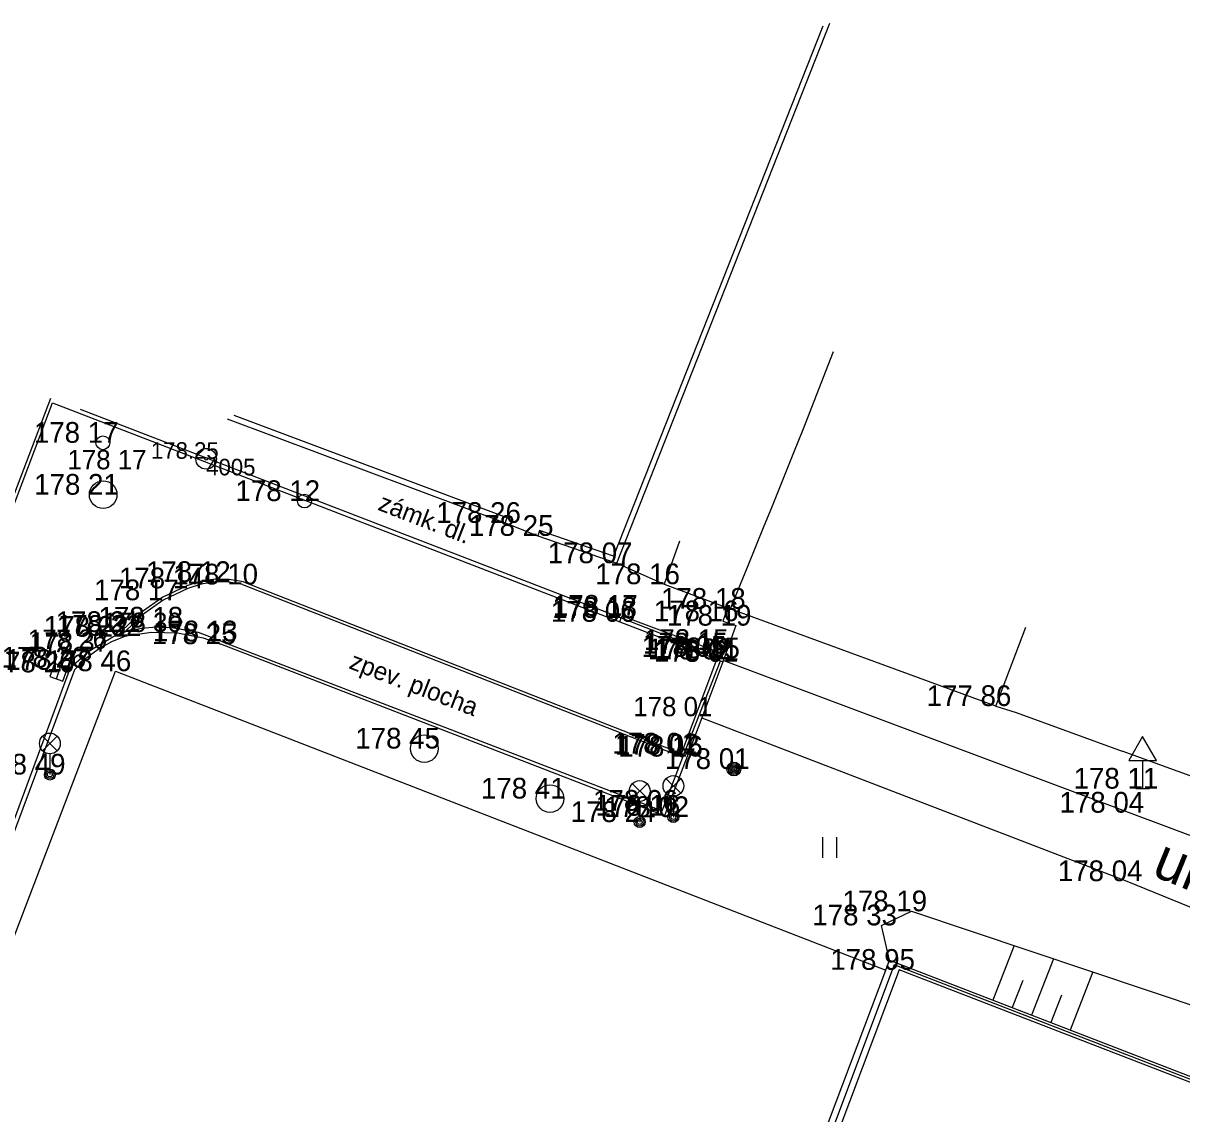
# Model space of a CAD drawing. Extents: x -537755 to -537431, y -1180722 to -1180510.
# Drawn here: x -537546.93 to -537504.97, y -1180552.16 to -1180512.68 of the extents above; entities that cross this region are included whole.
import ezdxf

# ---------------------------------------------------------------- set-up
doc = ezdxf.new("R2010")
doc.units = 0
for name, color, linetype in [('Vrstva 1', 7, 'Continuous'), ('Vrstva 10', 7, 'Continuous'), ('Vrstva 11', 7, 'Continuous'), ('Vrstva 14', 7, 'Continuous'), ('Vrstva 15', 7, 'Continuous'), ('Vrstva 21', 7, 'Continuous'), ('Vrstva 22', 7, 'Continuous'), ('Vrstva 23', 7, 'Continuous'), ('Vrstva 25', 7, 'Continuous'), ('Vrstva 27', 7, 'Continuous'), ('Vrstva 28', 7, 'Continuous'), ('Vrstva 3', 7, 'Continuous'), ('Vrstva 33', 7, 'Continuous'), ('Vrstva 34', 7, 'Continuous'), ('Vrstva 36', 7, 'Continuous'), ('Vrstva 40', 7, 'Continuous'), ('Vrstva 49', 7, 'Continuous'), ('Vrstva 7', 7, 'Continuous'), ('Vrstva 8', 7, 'Continuous')]:
    doc.layers.add(name, color=color, linetype=linetype)

msp = doc.modelspace()

# ---------------------------------------------------------------- linework, layer by layer
at = {"layer": 'Vrstva 1'}
for p, q in [((-537544.04, -1180527.87), (-537544.04, -1180527.87)), ((-537542.99, -1180528.83), (-537542.99, -1180528.83)), ((-537544.03, -1180529.75), (-537544.03, -1180529.75)), ((-537536.74, -1180529.98), (-537536.74, -1180529.98)), ((-537529.47, -1180530.77), (-537529.47, -1180530.77)), ((-537528.29, -1180531.24), (-537528.29, -1180531.24)), ((-537525.43, -1180532.23), (-537525.43, -1180532.23)), ((-537540.96, -1180533.14), (-537540.96, -1180533.14)), ((-537539.98, -1180532.91), (-537539.98, -1180532.91)), ((-537538.99, -1180533), (-537538.99, -1180533)), ((-537523.71, -1180532.99), (-537523.71, -1180532.99)), ((-537541.86, -1180533.57), (-537541.86, -1180533.57)), ((-537521.33, -1180533.88), (-537521.33, -1180533.88)), ((-537525.32, -1180534.35), (-537525.32, -1180534.35)), ((-537525.27, -1180534.21), (-537525.27, -1180534.21)), ((-537525.24, -1180534.13), (-537525.24, -1180534.13)), ((-537521.59, -1180534.33), (-537521.59, -1180534.33)), ((-537543.25, -1180534.72), (-537543.25, -1180534.72)), ((-537541.71, -1180534.72), (-537541.71, -1180534.72)), ((-537541.7, -1180534.56), (-537541.7, -1180534.56)), ((-537521.12, -1180534.49), (-537521.12, -1180534.49)), ((-537543.68, -1180534.89), (-537543.68, -1180534.89)), ((-537543.21, -1180534.86), (-537543.21, -1180534.86)), ((-537539.77, -1180535.16), (-537539.77, -1180535.16)), ((-537539.73, -1180535.06), (-537539.73, -1180535.06)), ((-537544.42, -1180535.33), (-537544.42, -1180535.33)), ((-537544.35, -1180535.43), (-537544.35, -1180535.43)), ((-537522.03, -1180535.62), (-537522.03, -1180535.62)), ((-537521.98, -1180535.5), (-537521.98, -1180535.5)), ((-537521.95, -1180535.37), (-537521.95, -1180535.37)), ((-537545.21, -1180536.01), (-537545.21, -1180536.01)), ((-537521.81, -1180535.71), (-537521.81, -1180535.71)), ((-537521.59, -1180535.8), (-537521.59, -1180535.8)), ((-537521.58, -1180535.75), (-537521.58, -1180535.75)), ((-537521.54, -1180535.67), (-537521.54, -1180535.67)), ((-537545.64, -1180536.18), (-537545.64, -1180536.18)), ((-537545.07, -1180536.09), (-537545.07, -1180536.09)), ((-537543.58, -1180536.14), (-537543.58, -1180536.14)), ((-537511.71, -1180537.4), (-537511.71, -1180537.4)), ((-537522.5, -1180537.77), (-537522.5, -1180537.77)), ((-537532.4, -1180538.94), (-537532.4, -1180538.94)), ((-537523.09, -1180539.12), (-537523.09, -1180539.12)), ((-537523, -1180539.16), (-537523, -1180539.16)), ((-537522.88, -1180539.23), (-537522.88, -1180539.23)), ((-537521.19, -1180539.68), (-537521.19, -1180539.68)), ((-537545.96, -1180539.88), (-537545.96, -1180539.88)), ((-537506.39, -1180540.39), (-537506.39, -1180540.39)), ((-537527.85, -1180540.75), (-537527.85, -1180540.75)), ((-537523.79, -1180541.19), (-537523.79, -1180541.19)), ((-537523.7, -1180541.37), (-537523.7, -1180541.37)), ((-537523.38, -1180541.42), (-537523.38, -1180541.42)), ((-537506.9, -1180541.26), (-537506.9, -1180541.26)), ((-537524.61, -1180541.6), (-537524.61, -1180541.6)), ((-537524.6, -1180541.6), (-537524.6, -1180541.6)), ((-537525.17, -1180543.28), (-537525.17, -1180543.28)), ((-537506.96, -1180543.74), (-537506.96, -1180543.74)), ((-537514.76, -1180544.83), (-537514.76, -1180544.83)), ((-537515.85, -1180545.34), (-537515.85, -1180545.34)), ((-537515.2, -1180546.95), (-537515.2, -1180546.95))]:
    msp.add_line(p, q, dxfattribs=at)
at = {"layer": 'Vrstva 10'}
for p, q in [((-537547.93, -1180531.88), (-537545.86, -1180526.42)), ((-537545.86, -1180526.42), (-537525.32, -1180534.35)), ((-537538.99, -1180533), (-537523.034, -1180539.249)), ((-537538.954, -1180532.907), (-537523.09, -1180539.12)), ((-537539.73, -1180535.06), (-537523.79, -1180541.19)), ((-537551.18, -1180552.11), (-537545.21, -1180536.01)), ((-537523.09, -1180539.12), (-537521.81, -1180535.71)), ((-537484.2, -1180549.75), (-537506.9, -1180541.26)), ((-537506.96, -1180543.74), (-537489.58, -1180550.85))]:
    msp.add_line(p, q, dxfattribs=at)
for points in [[(-537540.995, -1180533.046), (-537541.867, -1180533.458), (-537542.659, -1180534.009), (-537543.35, -1180534.682), (-537543.439, -1180534.787)], [(-537540.96, -1180533.14), (-537541.86, -1180533.57), (-537542.608, -1180534.096), (-537543.25, -1180534.72)], [(-537538.954, -1180532.907), (-537539.466, -1180532.816), (-537539.973, -1180532.809), (-537540.476, -1180532.882), (-537540.961, -1180533.032), (-537540.995, -1180533.046)], [(-537538.99, -1180533), (-537539.483, -1180532.915), (-537539.98, -1180532.91), (-537540.477, -1180532.985), (-537540.96, -1180533.14)], [(-537525.32, -1180534.35), (-537522.03, -1180535.62), (-537521.81, -1180535.71), (-537521.678, -1180535.764), (-537521.59, -1180535.8)], [(-537543.68, -1180534.89), (-537543.439, -1180534.787), (-537543.25, -1180534.72), (-537543.171, -1180534.695), (-537542.639, -1180534.577), (-537542.096, -1180534.538), (-537541.7, -1180534.56)], [(-537539.73, -1180535.06), (-537540.578, -1180534.741), (-537541.468, -1180534.577), (-537541.7, -1180534.56)], [(-537545.21, -1180536.01), (-537544.508, -1180535.393), (-537543.68, -1180534.89)]]:
    msp.add_lwpolyline(points, dxfattribs=at)
at = {"layer": 'Vrstva 11'}
for p, q in [((-537544.86, -1180526.65), (-537525.27, -1180534.21)), ((-537523.155, -1180531.435), (-537523.71, -1180532.99)), ((-537520.715, -1180532.385), (-537521.33, -1180533.88)), ((-537525.27, -1180534.21), (-537521.98, -1180535.5)), ((-537523.7, -1180541.37), (-537539.77, -1180535.16)), ((-537521.98, -1180535.5), (-537522.03, -1180535.62)), ((-537521.98, -1180535.5), (-537521.54, -1180535.67)), ((-537506.9, -1180541.26), (-537521.58, -1180535.75)), ((-537545.07, -1180536.09), (-537551.06, -1180552.15)), ((-537522.352, -1180537.827), (-537506.96, -1180543.74)), ((-537523, -1180539.16), (-537523.09, -1180539.12))]:
    msp.add_line(p, q, dxfattribs=at)
for points in [[(-537517.597, -1180524.573), (-537518.211, -1180526.157), (-537518.675, -1180527.344), (-537519.027, -1180528.232), (-537519.559, -1180529.563), (-537519.829, -1180530.227), (-537520.1, -1180530.89), (-537520.715, -1180532.385)], [(-537547.7, -1180530.94), (-537547.684, -1180530.893), (-537545.92, -1180526.26)], [(-537521.416, -1180533.848), (-537521.59, -1180534.33), (-537521.12, -1180534.49), (-537521.54, -1180535.67)], [(-537525.32, -1180534.35), (-537525.27, -1180534.21), (-537525.24, -1180534.13), (-537521.95, -1180535.37), (-537521.98, -1180535.5)], [(-537543.21, -1180534.86), (-537542.278, -1180534.725), (-537541.336, -1180534.749), (-537540.412, -1180534.932), (-537539.77, -1180535.16)], [(-537545.07, -1180536.09), (-537544.67, -1180535.685), (-537544.217, -1180535.339), (-537543.721, -1180535.06), (-537543.21, -1180534.86)], [(-537523.79, -1180541.19), (-537523.034, -1180539.249), (-537523, -1180539.16), (-537521.678, -1180535.764)], [(-537521.54, -1180535.67), (-537521.58, -1180535.75), (-537521.59, -1180535.8), (-537522.352, -1180537.827), (-537522.88, -1180539.23), (-537523.65, -1180541.24), (-537523.7, -1180541.37)]]:
    msp.add_lwpolyline(points, dxfattribs=at)
at = {"layer": 'Vrstva 14'}
msp.add_line((-537514.76, -1180544.83), (-537500.72, -1180549.53), dxfattribs=at)
msp.add_lwpolyline([(-537515.555, -1180546.598), (-537515.85, -1180545.34), (-537514.76, -1180544.83)], dxfattribs=at)
at = {"layer": 'Vrstva 15'}
for p, q in [((-537511.045, -1180546.074), (-537511.809, -1180548.048)), ((-537509.621, -1180546.55), (-537510.411, -1180548.589)), ((-537510.728, -1180547.332), (-537511.11, -1180548.319)), ((-537508.197, -1180547.027), (-537509.012, -1180549.131)), ((-537509.329, -1180547.873), (-537509.711, -1180548.86))]:
    msp.add_line(p, q, dxfattribs=at)
at = {"layer": 'Vrstva 21'}
for radius in [0.375, 0.05]:
    msp.add_circle((-537540.3, -1180528.45), radius, dxfattribs=at)
at = {"layer": 'Vrstva 25'}
for radius in [0.25, 0.2, 0.15, 0.1, 0.05]:
    msp.add_circle((-537521.19, -1180539.68), radius, dxfattribs=at)
at = {"layer": 'Vrstva 27'}
msp.add_line((-537545.721, -1180536.416), (-537545.559, -1180535.944), dxfattribs=at)
msp.add_lwpolyline([(-537545.485, -1180536.498), (-537545.322, -1180536.025), (-537545.795, -1180535.862), (-537545.958, -1180536.335)], close=True, dxfattribs=at)
for centre in [(-537544.03, -1180529.75), (-537532.4, -1180538.94), (-537527.85, -1180540.75)]:
    msp.add_circle(centre, 0.5, dxfattribs=at)
at = {"layer": 'Vrstva 28'}
for centre in [(-537544.04, -1180527.87), (-537536.74, -1180529.98)]:
    msp.add_circle(centre, 0.25, dxfattribs=at)
at = {"layer": 'Vrstva 33'}
for p, q in [((-537546.224, -1180539.021), (-537545.696, -1180538.491)), ((-537546.224, -1180538.491), (-537545.696, -1180539.021)), ((-537545.96, -1180539.13), (-537545.96, -1180539.88)), ((-537524.864, -1180540.741), (-537524.336, -1180540.211)), ((-537524.864, -1180540.211), (-537524.336, -1180540.741)), ((-537523.645, -1180540.56), (-537523.115, -1180540.03)), ((-537523.645, -1180540.03), (-537523.115, -1180540.56)), ((-537523.38, -1180540.67), (-537523.38, -1180541.42)), ((-537524.6, -1180540.85), (-537524.6, -1180541.6))]:
    msp.add_line(p, q, dxfattribs=at)
for centre, radius in [((-537545.96, -1180538.756), 0.375), ((-537545.96, -1180539.881), 0.2), ((-537545.96, -1180539.881), 0.145), ((-537545.96, -1180539.881), 0.0876), ((-537524.6, -1180540.476), 0.375), ((-537523.38, -1180540.295), 0.375), ((-537524.6, -1180541.601), 0.2), ((-537524.6, -1180541.601), 0.145), ((-537524.6, -1180541.601), 0.0876), ((-537523.38, -1180541.42), 0.2), ((-537523.38, -1180541.42), 0.145), ((-537523.38, -1180541.42), 0.0876)]:
    msp.add_circle(centre, radius, dxfattribs=at)
at = {"layer": 'Vrstva 34'}
for p, q in [((-537506.39, -1180539.372), (-537506.39, -1180540.39)), ((-537506.64, -1180540.39), (-537506.14, -1180540.39))]:
    msp.add_line(p, q, dxfattribs=at)
msp.add_lwpolyline([(-537506.89, -1180539.372), (-537505.89, -1180539.372), (-537506.39, -1180538.506)], close=True, dxfattribs=at)
at = {"layer": 'Vrstva 36'}
for p, q in [((-537517.967, -1180542.898), (-537517.967, -1180542.148)), ((-537517.467, -1180542.898), (-537517.467, -1180542.148))]:
    msp.add_line(p, q, dxfattribs=at)
at = {"layer": 'Vrstva 7'}
for p, q in [((-537517.97, -1180512.793), (-537525.546, -1180531.978)), ((-537525.43, -1180532.23), (-537517.71, -1180512.68)), ((-537529.4, -1180530.583), (-537539.284, -1180526.882)), ((-537525.546, -1180531.978), (-537528.225, -1180531.051)), ((-537525.43, -1180532.23), (-537523.71, -1180532.99)), ((-537511.71, -1180537.4), (-537521.33, -1180533.88)), ((-537511.71, -1180537.4), (-537510.621, -1180534.545)), ((-537550.4, -1180553.96), (-537543.58, -1180536.14)), ((-537543.58, -1180536.14), (-537515.69, -1180546.957)), ((-537511.71, -1180537.4), (-537510.966, -1180537.633)), ((-537518.01, -1180553.12), (-537515.69, -1180546.957)), ((-537515.381, -1180546.773), (-537517.835, -1180553.292)), ((-537515.2, -1180546.95), (-537517.457, -1180552.946)), ((-537515.69, -1180546.957), (-537515.555, -1180546.598)), ((-537515.555, -1180546.598), (-537481.76, -1180559.68)), ((-537481.796, -1180559.773), (-537515.381, -1180546.773)), ((-537501.7, -1180552.176), (-537515.2, -1180546.95))]:
    msp.add_line(p, q, dxfattribs=at)
for points in [[(-537539.54, -1180527), (-537529.47, -1180530.77)], [(-537529.47, -1180530.77), (-537529.4, -1180530.583)], [(-537528.225, -1180531.051), (-537528.29, -1180531.24), (-537525.43, -1180532.23)], [(-537479.535, -1180549.052), (-537507.134, -1180539.034)]]:
    msp.add_lwpolyline(points, dxfattribs=at)
at = {"layer": 'Vrstva 8'}
for p, q in [((-537529.47, -1180530.77), (-537528.29, -1180531.24)), ((-537510.966, -1180537.633), (-537507.134, -1180539.034))]:
    msp.add_line(p, q, dxfattribs=at)
msp.add_lwpolyline([(-537523.71, -1180532.99), (-537521.416, -1180533.848), (-537521.33, -1180533.88)], dxfattribs=at)

# ---------------------------------------------------------------- texts
at = {"layer": 'Vrstva 22'}
msp.add_text('178.25 ', height=0.6, dxfattribs=at).set_placement((-537542.3, -1180528.45))
at = {"layer": 'Vrstva 23'}
msp.add_text('4005', height=0.6, dxfattribs=at).set_placement((-537540.3, -1180529.05))
at = {"layer": 'Vrstva 3'}
for s, height, p in [('178 17 ', 0.75, (-537546.54, -1180527.87)), ('178 17 ', 0.7, (-537545.324, -1180528.83)), ('178 21 ', 0.75, (-537546.53, -1180529.75)), ('178 12 ', 0.75, (-537539.24, -1180529.98)), ('178 26 ', 0.75, (-537531.97, -1180530.77)), ('178 25 ', 0.75, (-537530.79, -1180531.24)), ('178 07 ', 0.75, (-537527.93, -1180532.23)), ('178 12 ', 0.75, (-537542.48, -1180532.91)), ('178 10 ', 0.75, (-537541.49, -1180533)), ('178 16 ', 0.75, (-537526.21, -1180532.99)), ('178 14 ', 0.75, (-537543.46, -1180533.14)), ('178 17 ', 0.75, (-537544.36, -1180533.57)), ('178 18 ', 0.75, (-537523.83, -1180533.88)), ('178 18 ', 0.75, (-537527.77, -1180534.21)), ('178 17 ', 0.75, (-537527.74, -1180534.13)), ('178 21 ', 0.75, (-537545.75, -1180534.72)), ('178 18 ', 0.75, (-537544.2, -1180534.56)), ('178 06 ', 0.75, (-537527.82, -1180534.35)), ('178 16 ', 0.75, (-537524.09, -1180534.33)), ('178 19 ', 0.75, (-537523.62, -1180534.49)), ('178 22 ', 0.75, (-537546.18, -1180534.89)), ('178 32 ', 0.75, (-537545.71, -1180534.86)), ('178 30 ', 0.7, (-537544.044, -1180534.72)), ('178 25 ', 0.75, (-537542.27, -1180535.16)), ('178 13 ', 0.75, (-537542.23, -1180535.06)), ('178 26 ', 0.7, (-537546.753, -1180535.33)), ('178 37 ', 0.7, (-537546.684, -1180535.43)), ('178 15 ', 0.75, (-537524.48, -1180535.5)), ('178 15 ', 0.75, (-537524.45, -1180535.37)), ('178 05 ', 0.75, (-537524.53, -1180535.62)), ('178 02 ', 0.75, (-537524.31, -1180535.71)), ('178 01 ', 0.75, (-537524.09, -1180535.8)), ('178 01 ', 0.75, (-537524.08, -1180535.75)), ('178 15 ', 0.75, (-537524.04, -1180535.67)), ('178 26 ', 0.75, (-537548.14, -1180536.18)), ('178 26 ', 0.75, (-537547.71, -1180536.01)), ('178 37 ', 0.75, (-537547.57, -1180536.09)), ('178 46 ', 0.75, (-537546.08, -1180536.14)), ('177 86 ', 0.75, (-537514.21, -1180537.4)), ('178 01 ', 0.7, (-537524.833, -1180537.77)), ('178 45 ', 0.75, (-537534.9, -1180538.94)), ('178 01 ', 0.75, (-537525.59, -1180539.12)), ('178 02 ', 0.75, (-537525.5, -1180539.16)), ('178 16 ', 0.75, (-537525.38, -1180539.23)), ('178 01 ', 0.75, (-537523.69, -1180539.68)), ('178 49 ', 0.75, (-537548.46, -1180539.88)), ('178 11 ', 0.75, (-537508.89, -1180540.39)), ('178 41 ', 0.75, (-537530.35, -1180540.75)), ('178 06 ', 0.75, (-537526.29, -1180541.19)), ('178 16 ', 0.75, (-537526.2, -1180541.37)), ('178 02 ', 0.75, (-537525.88, -1180541.42)), ('178 04 ', 0.75, (-537509.4, -1180541.26)), ('178 24 ', 0.75, (-537527.1, -1180541.6)), ('178 04 ', 0.75, (-537509.46, -1180543.74)), ('178 19 ', 0.75, (-537517.26, -1180544.83)), ('178 33 ', 0.75, (-537518.35, -1180545.34)), ('178 95 ', 0.75, (-537517.7, -1180546.95))]:
    msp.add_text(s, height=height, dxfattribs=at).set_placement(p)
at = {"layer": 'Vrstva 40'}
for s, rotation, p in [('zámk. dl.', 338.8978, (-537534.119, -1180530.289)), ('zpev. plocha', 338.9649, (-537535.166, -1180536.025))]:
    msp.add_text(s, height=0.65, rotation=rotation, dxfattribs=at).set_placement(p)
at = {"layer": 'Vrstva 49'}
msp.add_text('ul. V Zahradách', height=1.5, rotation=337.751, dxfattribs=at).set_placement((-537506.106, -1180543.511))

doc.saveas('drawing.dxf')
